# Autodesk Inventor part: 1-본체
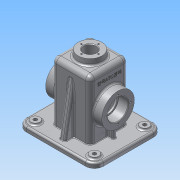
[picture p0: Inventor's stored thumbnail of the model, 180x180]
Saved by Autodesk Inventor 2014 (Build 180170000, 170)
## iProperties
Created: 2015-12
Part Number: 1-본체
Material: 알루미늄 6061
Document SubType Name: Modeling
Designer: Administrator
Density: 2.71 g/cm^3
Appearance: 알루미늄 - 평지
Mass: 789.44 g
Surface Area: 912.75 cm^2
Volume: 291.306 cm^3
Author: Administrator
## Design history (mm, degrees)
sketch "스케치1"
  geometry: L1 (65, -57.5)-(-65, -57.5); L2 (-65, -57.5)-(-65, 57.5); L3 (-65, 57.5)-(65, 57.5); L4 (65, 57.5)-(65, -57.5); L5 (65, -57.5)-(-65, 57.5); L6 (-65, -57.5)-(65, 57.5); 1 further point
  constraints: 12 end point, 2 midpoint, 2 parallel, 1 horizontal, 1 perpendicular
  dimensions: "d0" = 130 distance of L2.end L3.end; "d1" = 115 distance of L3.end L1.start
extrude "돌출1" new body sketch "스케치1" distance "d2" = 8; taper "d3" = 0 deg
sketch "스케치2"
  geometry: L1 (32.5, -32.5)-(-32.5, -32.5); L2 (-32.5, -32.5)-(-32.5, 32.5); L3 (-32.5, 32.5)-(32.5, 32.5); L4 (32.5, 32.5)-(32.5, -32.5); L5 (32.5, -32.5)-(-32.5, 32.5); L6 (-32.5, -32.5)-(32.5, 32.5); 1 further point
  constraints: 12 end point, 2 midpoint, 2 parallel, 1 horizontal, 1 perpendicular
  dimensions: "d4" = 65 distance of L2.end L3.end; "d5" = 65 distance of L3.end L1.start
extrude "돌출2" join sketch "스케치2" distance "d6" = 100; taper "d7" = 0 deg
node "작업 평면1"
sketch "스케치3"
  geometry: L1 (57.5, 8)-(-57.5, 8) reference; L2 (-57.5, 0)-(-57.5, 8) reference; L3 (57.5, 0)-(57.5, 8) reference; L4 (-47.5, 8)-(-31.379, 99.424); L5 (31.379, 99.424)-(47.5, 8); L6 (-31.379, 99.424)-(31.379, 99.424); L7 (-47.5, 8)-(47.5, 8); 1 further point
  constraints: 8 end point, 2 point on line, 1 collinear, 1 perpendicular
  dimensions: "d9" = 10 deg angle of L2 L4; "d10" = 10 distance from line of L4.start L2; "d11" = 10 distance of L1.start L5.end; "d12" = 10 deg angle of L3 L5; "d13" = 62.75886 distance of L4.end L5.start
extrude "돌출3" join sketch "스케치3" stored distance "d14" = 10; taper "d15" = 0 deg
fillet "모깎기1" dims "d16" = 8
fillet "모깎기2" dims "d17" = 8
node "작업 평면2"
sketch "스케치5"
  geometry: L1 (-8, -33)-(-8, 82) reference; C1 r 27.5 at (45, 24.5); 2 further points
  constraints: 1 centre point, 1 horizontal alignment, 1 midpoint
  dimensions: "d23" = 53 distance from line of C1.centre L1; "d24" = 55 diameter of C1
extrude "돌출5" join sketch "스케치5" stored distance "d25" = 10; taper "d26" = 0 deg
node "작업 평면3"
node "작업 평면4"
sketch "스케치6"
  geometry: L1 (24.5, 32.5)-(5, 32.5) reference; L2 (-5, 32.5)-(-24.5, 32.5) reference; L3 (5, -32.5)-(24.5, -32.5) reference; L4 (-24.5, -32.5)-(-5, -32.5) reference; L5 (32.5, -24.5)-(32.5, 24.5) reference; L6 (-32.5, 24.5)-(-32.5, -24.5) reference; L7 (27.5, 27.5)-(-27.5, 27.5); L8 (-27.5, 27.5)-(-27.5, -27.5); L9 (-27.5, -27.5)-(27.5, -27.5); L10 (27.5, -27.5)-(27.5, 27.5); L11 (27.5, 27.5)-(-27.5, -27.5); L12 (-27.5, 27.5)-(27.5, -27.5); 1 further point
  constraints: 12 end point, 2 midpoint, 2 parallel, 1 horizontal, 1 perpendicular
  dimensions: "d27" = 55 distance of L9.end L7.start; "d28" = 55 distance of L8.end L9.end
extrude "돌출6" cut sketch "스케치6" distance "d29" = 103; taper "d30" = 0 deg
fillet "모깎기5" dims "d38" = 3
fillet "모깎기6" dims "d39" = 3
fillet "모깎기7" dims "d40" = 3
hole "구멍1" diameter "d43" = 30; stored, may be unused: countersink angle "d47" = 90 deg, drill point angle "d49" = 118 deg; dims "d41" = 10, "d42" = 10, "d44" = 6, "d45" = 35, "d46" = 17, "d48" = 8
sketch "스케치8" dims "d51" = 42
  geometry: C1 r 17.5 at (0, 0) reference; C2 r 27.5 at (0, 0) reference; 6 further points
  constraints: 2 vertical alignment, 1 coincident, 7 other
  dimensions: "d54" = 360 deg dimension on C1.centre point (0, 21) (derived)
hole "구멍2" sketch "스케치8" at (0, 21), (-21, 0), (0, -21), (21, 0) diameter "d56" = 3.242; stored, may be unused: countersink angle "d60" = 90 deg, drill point angle "d62" = 118 deg; dims "d57" = 8, "d58" = 35, "d59" = 17, "d61" = 10
fillet "모깎기8" dims "d63" = 0.3
sketch "스케치9"
  geometry: L1 (-27.5, -24.5)-(-27.5, 24.5) reference; L2 (-24.5, 27.5)-(24.5, 27.5) reference; L3 (27.5, 24.5)-(27.5, -24.5) reference; L4 (24.5, -27.5)-(-24.5, -27.5) reference; L5 (-60, -52.5)-(60, -52.5); L6 (60, -52.5)-(60, 52.5); L7 (60, 52.5)-(-60, 52.5); L8 (-60, 52.5)-(-60, -52.5); L9 (-60, -52.5)-(60, 52.5); L10 (60, -52.5)-(-60, 52.5); A1 r 3 centre (-24.5, 24.5) between (-24.5, 27.5) and (-27.5, 24.5) reference; A2 r 3 centre (24.5, 24.5) between (27.5, 24.5) and (24.5, 27.5) reference; A3 r 3 centre (24.5, -24.5) between (24.5, -27.5) and (27.5, -24.5) reference; A4 r 3 centre (-24.5, -24.5) between (-27.5, -24.5) and (-24.5, -27.5) reference; 1 further point
  constraints: 12 end point, 2 midpoint, 2 parallel, 1 horizontal, 1 perpendicular
  dimensions: "d66" = 120 distance of L6.end L7.end; "d67" = 105 distance of L5.end L6.end
extrude "돌출8" join sketch "스케치9" distance "d68" = 2; taper "d69" = 0 deg
fillet "모깎기11" dims "d70" = 15
sketch "스케치10"
  geometry: C1 r 7.5 at (-50, 42.5); C2 r 7.5 at (50, 42.5); C3 r 7.5 at (50, -42.5); C4 r 7.5 at (-50, -42.5); A1 r 15 centre (-50, -42.5) between (-65, -42.5) and (-50, -57.5) reference; A2 r 15 centre (50, -42.5) between (50, -57.5) and (65, -42.5) reference; A3 r 15 centre (50, 42.5) between (65, 42.5) and (50, 57.5) reference; A4 r 15 centre (-50, 42.5) between (-50, 57.5) and (-65, 42.5) reference; 1 further point
  constraints: 4 centre point, 4 coincident, 3 equal radius
  dimensions: "d71" = 15 diameter of C1
extrude "돌출9" join sketch "스케치10" distance "d72" = 3; taper "d73" = 0 deg
fillet "모깎기12" dims "d74" = 3
sketch "스케치11"
  geometry: C1 r 7.5 at (0, 0) reference; C2 r 7.5 at (-100, 85) reference; C3 r 7.5 at (0, 85) reference; C4 r 7.5 at (-100, 0) reference; 5 further points
  constraints: 4 coincident
hole "구멍3" sketch "스케치11" at (-100, 85), (0, 85), (0, 0), (-100, 0) diameter "d75" = 6; stored, may be unused: countersink angle "d79" = 90 deg, drill point angle "d81" = 0 deg; dims "d76" = 8, "d77" = 35, "d78" = 17, "d80" = 10
node "작업 평면5"
sketch "스케치15"
  geometry: L1 (-32.5, -24.5)-(-32.5, 24.5) reference; L2 (-47.5, -27.5)-(-47.5, 27.5) reference; L3 (-42.5, 3)-(-32.5, 3); L4 (-32.5, 3)-(-32.5, -3); L5 (-32.5, -3)-(-42.5, -3); L6 (-42.5, -3)-(-42.5, 3); L7 (-42.5, 3)-(-32.5, -3); L8 (-32.5, 3)-(-42.5, -3); 4 further points
  constraints: 12 end point, 4 midpoint, 2 parallel, 1 collinear, 1 horizontal, 1 horizontal alignment, 1 perpendicular
  dimensions: "d112" = 6 distance of L5.end L3.start; "d113" = 10 distance between parallel lines of L1 L6
extrude "돌출12" join sketch "스케치15" stored distance "d114" = 10; taper "d115" = 0 deg
node "작업 평면6"
fillet "모깎기14" dims "d116" = 3
fillet "모깎기15" dims "d117" = 1
fillet "모깎기16" dims "d118" = 3
chamfer "모따기1" distance "d119" = 1; stored, may be unused: second distance "d120" = 2, angle "d121" = 45 deg
fillet "모깎기17" dims "d122" = 10
node "작업 평면7"
sketch "스케치17"
  geometry: L1 (-24.5, -24.5)-(-24.5, 24.5) reference; L2 (24.5, -24.5)-(-24.5, -24.5) reference; L3 (24.5, 24.5)-(24.5, -24.5) reference; L4 (-24.5, 24.5)-(24.5, 24.5) reference; C1 r 20 at (0, 0); 1 further point
  constraints: 1 centre point, 1 coincident
  dimensions: "d127" = 40 diameter of C1
extrude "돌출13" join sketch "스케치17" stored distance "d128" = 10; taper "d129" = 5 deg
fillet "모깎기18" dims "d130" = 3
sketch "스케치18"
  geometry: L1 (-18, 4.5)-(-18, 44.5) reference; A1 r 30.5 centre (47, 24.5) between (28.834, 49) and (28.834, 0) reference; 2 further points
  constraints: 1 horizontal alignment, 1 other
  dimensions: "d131" = 26 distance from line of point (8, 24.5) L1
feature "엠보싱2" sketch "스케치18" dims "d132" = 0.5, "d133" = 0
hole "구멍6" diameter "d136" = 21; stored, may be unused: countersink angle "d140" = 90 deg, drill point angle "d142" = 118 deg; dims "d134" = 10, "d135" = 10, "d137" = 6, "d138" = 4, "d139" = 2, "d141" = 8
sketch "스케치19" dims "d143" = 29
  geometry: C1 r 10.5 at (0, 0) reference; C2 r 20 at (0, 0) reference; 5 further points
  constraints: 2 vertical alignment, 1 coincident, 7 other
  dimensions: "d146" = 360 deg dimension on C1.centre point (0, 14.5) (derived)
hole "구멍7" sketch "스케치19" at (0, 14.5), (-14.5, 0), (0, -14.5), (14.5, 0) diameter "d148" = 2.459; stored, may be unused: countersink angle "d152" = 90 deg, drill point angle "d154" = 118 deg; dims "d149" = 7, "d150" = 4, "d151" = 2, "d153" = 9
chamfer "모따기2" distance "d155" = 1; stored, may be unused: second distance "d156" = 2, angle "d157" = 45 deg
node "솔리드1"
mirror "대칭1"
mirror "대칭2"
mirror "대칭4"
node "투영된 루프1"
node "투영된 루프2"
node "투영된 루프3"
node "투영된 루프5"
other parameters: "d8" = 0, "d22" = 15, "d33" = 0
